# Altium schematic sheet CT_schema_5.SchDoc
size 302 x 256 mm
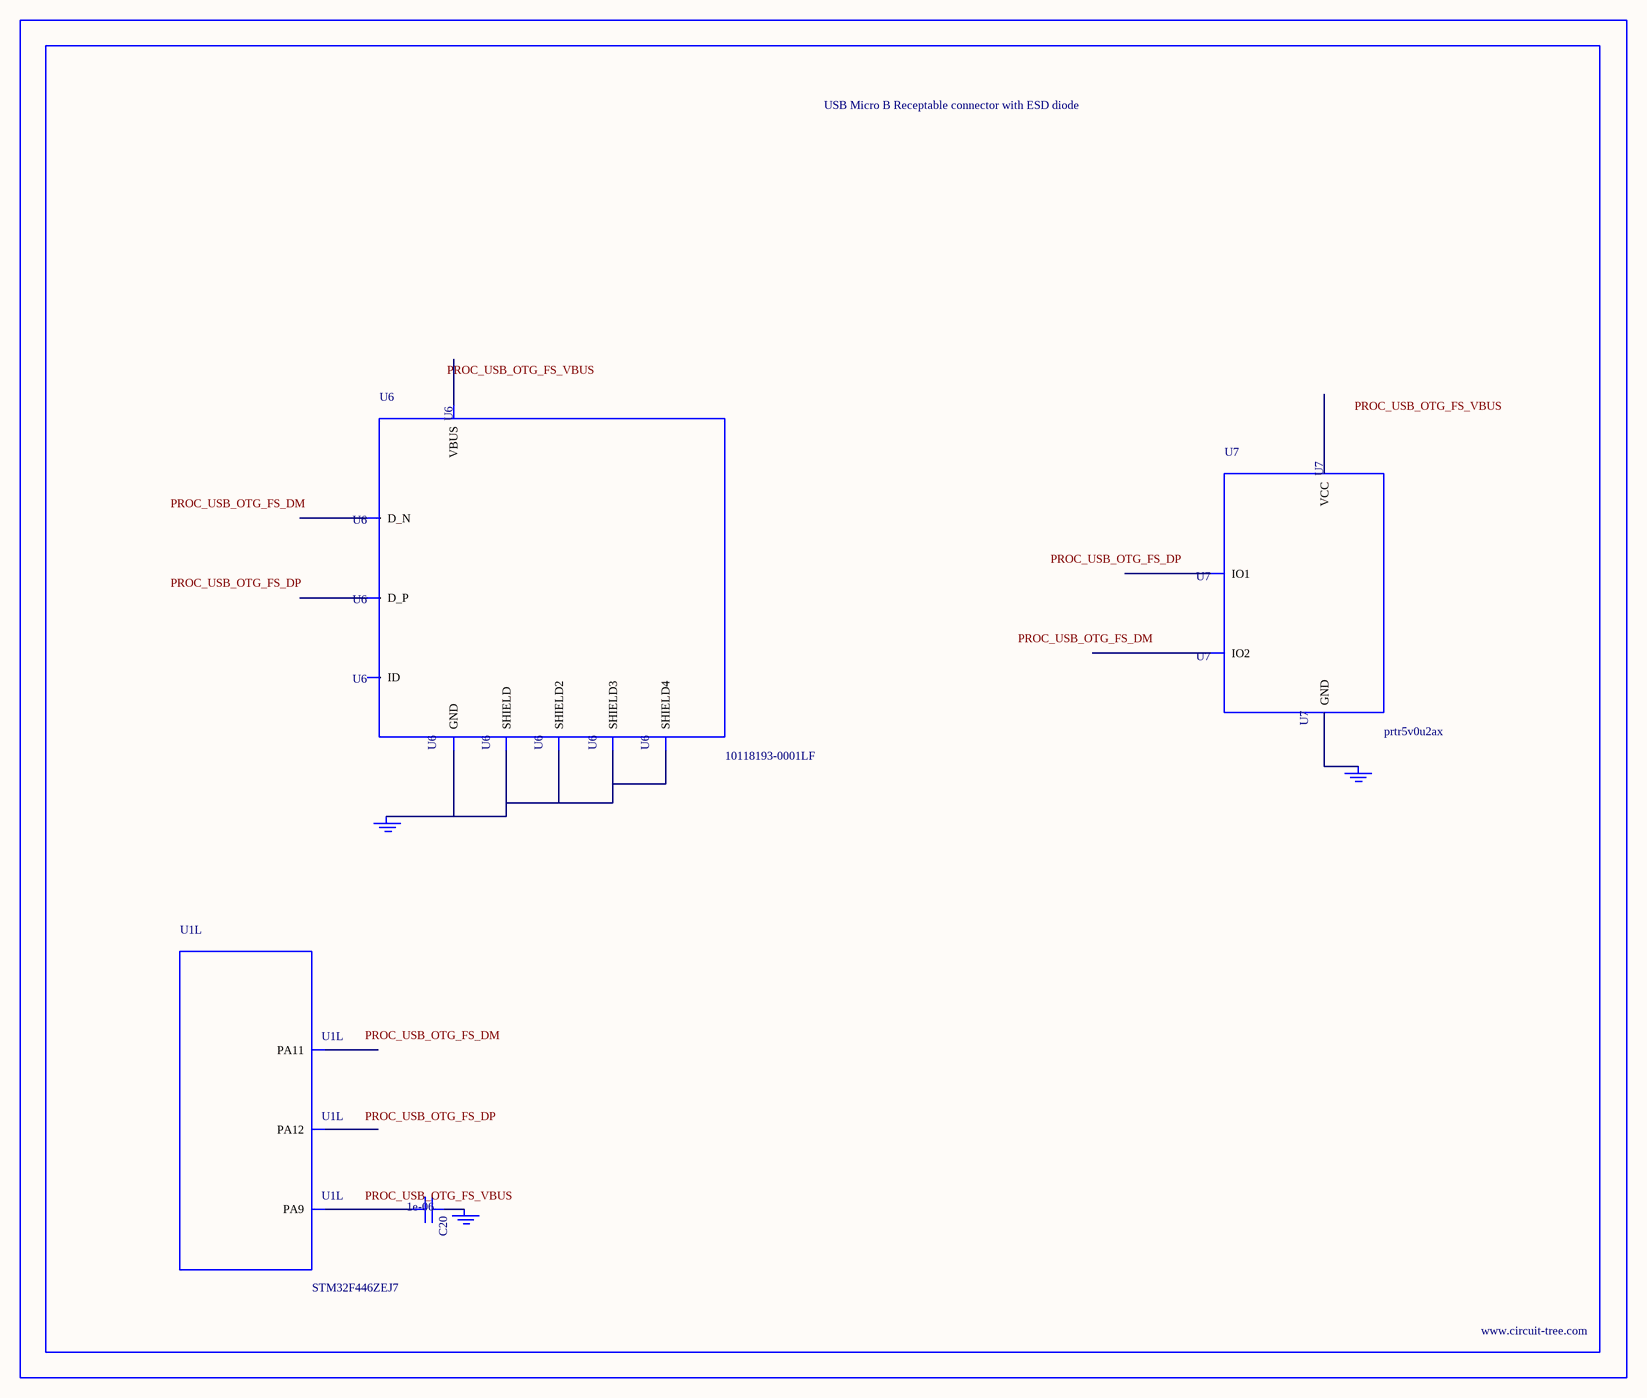
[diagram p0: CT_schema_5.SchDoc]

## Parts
BORDER4  (no value)
C20  1e-06  [C0603]
GND_INSTANCE_4_0  (no value)
GND_INSTANCE_4_1  (no value)
GND_INSTANCE_4_2  (no value)
U1  STM32F446ZEJ7  [UFBGA144]  (part L of 12)
U6  10118193-0001LF  [FCI_10118193-0001LF]
U7  prtr5v0u2ax  [SOT143B]

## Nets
NetC20_1: C20.1 GND_INSTANCE_4_1.0(GND)
NetC20_2: C20.2 U1.D12(PA9)
NetGND_INSTANCE_4_0_0: GND_INSTANCE_4_0.0(GND) U6.5(GND) U6.6(SHIELD) U6.7(SHIELD2) U6.8(SHIELD3) U6.9(SHIELD4)
NetGND_INSTANCE_4_2_0: GND_INSTANCE_4_2.0(GND) U7.1(GND)

Not connected (* = marked no-connect by the designer): U1 B12(PA12) C12(PA11); U6 1(VBUS) 2(D_N) 3(D_P) 4(ID); U7 2(IO1) 3(IO2) 4(VCC)

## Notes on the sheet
- Labels drawn without touching a wire or pin: PROC_USB_OTG_FS_DM, PROC_USB_OTG_FS_DP, PROC_USB_OTG_FS_VBUS

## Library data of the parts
BORDER4 = BORDER_PAGE4
C20 = C0603C105K3RACTU
GND_INSTANCE_4_0-GND_INSTANCE_4_2 = GND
